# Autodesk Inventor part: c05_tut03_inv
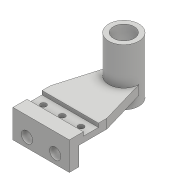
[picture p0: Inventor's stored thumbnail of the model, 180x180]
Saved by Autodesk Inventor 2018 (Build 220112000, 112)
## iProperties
Created: 2017-04
Part Number: c05_tut03_inv
Material: Generic
Document SubType Name: Modeling
Designer: CADCIM 00
Density: 1 g/cm^3
Appearance: Default
Author: CADCIM 00
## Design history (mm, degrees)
sketch "Sketch1"
  geometry: L1 (0, 0)-(-9, 0); L2 (-9, 0)-(-9, -4); L3 (-9, -4)-(-25, -4); L4 (-25, -4)-(-25, 0); L5 (-25, 0)-(-40, 0); L6 (-40, 0)-(-40, -30); L7 (-40, -30)-(-30, -30); L8 (-30, -30)-(-30, -10); L9 (-30, -10)-(0, -10); L10 (0, -10)-(0, 0)
  constraints: 20 end point, 7 perpendicular, 2 point on line, 1 horizontal
  dimensions: "d0" = 4 distance of L1.end L2.end; "d1" = 16 distance of L2.end L3.end; "d2" = 4 distance of L3.end L4.end; "d3" = 15 distance of L4.end L5.end; "d4" = 30 distance of L5.end L6.end; "d5" = 10 distance of L6.end L7.end; "d6" = 10 distance of L9.end L1.start; "d7" = 40 distance between parallel lines of L10 L6
extrude "Extrusion1" new body sketch "Sketch1" stored distance "d8" = 60; taper "d9" = 0 deg
sketch "Sketch2"
  geometry: L1 (0, 9)-(60, 9) reference; L2 (0, 9)-(14, 57); L3 (14, 57)-(46, 57); L4 (46, 57)-(60, 9); L5 (60, 9)-(0, 9); L6 (30, 9)-(30, 57)
  constraints: 10 end point, 2 parallel, 1 midpoint, 1 vertical
  dimensions: "d10" = 48 distance between parallel lines of L3 L1; "d11" = 32 distance of L2.end L3.end
extrude "Extrusion2" join sketch "Sketch2" distance "d12" = 10; taper "d13" = 0 deg
workplane "Work Plane1"
sketch "Sketch3"
  geometry: L1 (46, 78)-(14, 78) reference; 2 further points
  constraints: 1 horizontal alignment, 1 midpoint, 2 other
extrude "Extrusion3" join sketch "Sketch3" distance "d15" = 60; taper "d16" = 0 deg
sketch "Sketch4"
  geometry: C1 r 11 at (0, 0); 1 further point
  constraints: 1 centre point
  dimensions: "d17" = 22 diameter of C1
extrude "Extrusion4" cut sketch "Sketch4" distance "d18" = 60; taper "d19" = 0 deg
sketch "Sketch5"
  geometry: L1 (0, 0)-(0, 16) reference; L2 (0, -15)-(60, -15) reference; C1 r 3 at (10, 7.5); C2 r 3 at (30, 7.5); C3 r 3 at (50, 7.5); 1 further point
  constraints: 3 centre point, 2 equal radius, 2 horizontal alignment
  dimensions: "d20" = 6 diameter of C1; "d21" = 10 distance from line of L1 C1.centre; "d22" = 20 distance of C1.centre C2.centre; "d23" = 20 distance of C2.centre C3.centre; "d24" = 22.5 distance from line of L2 C1.centre
extrude "Extrusion5" cut sketch "Sketch5" distance "d25" = 60; taper "d26" = 0 deg
sketch "Sketch6"
  geometry: L1 (0, 0)-(0, 30) reference; L2 (0, 0)-(60, 0) reference; C1 r 6 at (15, 10); C2 r 6 at (45, 10); 1 further point
  constraints: 2 centre point, 1 equal radius, 1 horizontal alignment
  dimensions: "d27" = 15 distance from line of L1 C1.centre; "d28" = 12 diameter of C1; "d29" = 30 distance of C2.centre C1.centre; "d30" = 10 distance from line of L2 C1.centre
extrude "Extrusion6" cut sketch "Sketch6" stored distance "d31" = 60; taper "d32" = 0 deg
body "Solid1"
